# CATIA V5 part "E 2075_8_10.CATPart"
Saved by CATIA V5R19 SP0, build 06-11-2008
Nomenclature: E 2075_8_10
Description: PART-E 2075_8_10-DESC
Property "Hersteller": "Meusburger"
Property "Material": "2.0401 (CuZn)"
Property "Bestellnummer": "E2075/8/10"
Property "Teilenummer": "E2075/8/10"
Property "Beschreibung": "Verschlussschraube zylindrisch _ Threaded plug, cylindrical"
Material "Brass": density 8216 kg/m3, Young's modulus 1.31e+11 Pa, Poisson ratio 0.35, thermal expansion 1.67e-05 1/K
Bounding box of the stored display mesh (mm): x -5 to 5, y -4.99 to 4.99, z -8 to 0
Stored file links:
  G:\UTB\Kombinované\Bakalářská práce\Catia\FORMA\E 2075_8_10.CATPart
  D:\Aplikace\CATIA\Nová složka\win_b64\startup\materials\Catalog.CATMaterial
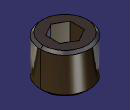
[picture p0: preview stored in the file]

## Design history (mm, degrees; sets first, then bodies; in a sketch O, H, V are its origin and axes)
Body1 "E 2075_8_10" (main body)
  Solid1: solid without history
